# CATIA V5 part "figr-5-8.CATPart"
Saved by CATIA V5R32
Part number: Part1
Bounding box of the stored display mesh (mm): x 0 to 150, y -70 to 70, z -150 to 69.804
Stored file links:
  D:\PROJECTS\Project 2022\CATIA V5 6R 2022\Resources\Part Files\c05_catia_v5_6r2022_prt\figr-5-8.CATPart
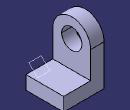
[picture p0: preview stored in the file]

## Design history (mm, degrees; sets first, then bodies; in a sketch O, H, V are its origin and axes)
Set1
  Plane1: type Angle, RefPlane face of Pad2, Direction edge of Pad2, Angle -45
Body1 (main body)
  Sketch1 on yz-plane, origin (0, 0, 0), H (0, 1, 0), V (0, 0, 1)
    arc A1 centre (0, 0) radius 70 from (70, 0) to (-70, 0) ccw
    point P1 (70, 0)
    point P2 (-70, 0)
    line L1 (-70, 0) -> (-70, -150)
    line L2 (-70, -150) -> (70, -150)
    line L3 (70, -150) -> (70, 0)
    circle A2 centre (0, 0) radius 37.5
    radius A1 = 70
    radius A2 = 37.5
    distance O L2 = 150
    coincidence: P1 H, P2 H
    tangency: L1 A1, L3 A1
    horizontal: L2 H
  Pad1: profile Sketch1, direction (1, 0, 0), length 50
  Sketch2 on face of Pad1, origin (50, 0, 0), H (0, 1, 0), V (0, 0, 1)
    line L1 (-70, -150) -> (70, -150)
    line L2 (70, -150) -> (70, -100)
    line L3 (70, -100) -> (-70, -100)
    line L4 (-70, -100) -> (-70, -150)
    reference projected line E1 (-70, -150) -> (70, -150) from edge [face of Pad1 | face of Pad1]
    reference projected line E2 (-70, 0) -> (-70, -150) from edge [face of Pad1 | face of Pad1]
    reference projected line E3 (70, -150) -> (70, 0) from edge [face of Pad1 | face of Pad1]
    length L2 = 50
    horizontal: L1 H, L3 H
    vertical: L2 V, L4 V
    coincidence: L1 E1, E2 L4, L2 E3
  Pad2: profile Sketch2, direction (1, 0, 0), length 100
